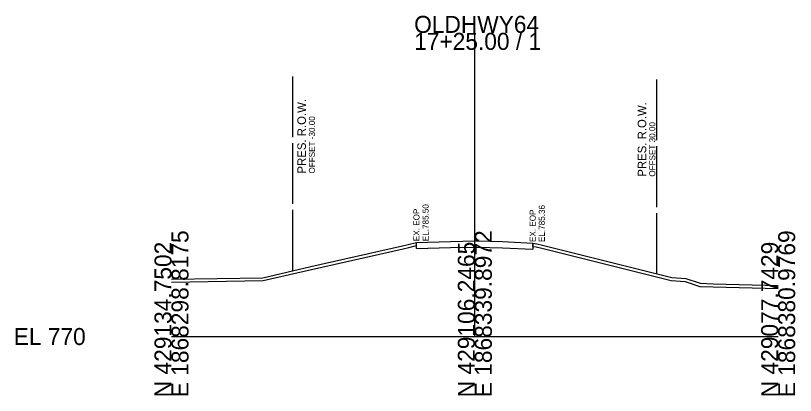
# Model space of a CAD drawing. Extents: x -452 to 3103, y -29 to 1600.
# Drawn here: x 2974.3 to 3102.8, y -16.7 to 45.8 of the extents above; entities that cross this region are included whole.
import ezdxf

# ---------------------------------------------------------------- set-up
doc = ezdxf.new("R2010")
doc.units = 0
for name, color, linetype in [('DESIGN - SHEET - Light Grid', 7, 'Continuous'), ('SURVEY - GROUND - Bottom of Topsoil Layer', 7, 'Continuous'), ('SURVEY - GROUND - Existing Pavement Layer', 7, 'Continuous'), ('SURVEY - GROUND - Existing Pavement Text', 7, 'Continuous'), ('SURVEY - GROUND - Top of Ground', 7, 'Continuous'), ('SURVEY - PROPERTY - ROW Lines', 7, 'Continuous'), ('SURVEY - PROPERTY - ROW Lines Text', 7, 'Continuous')]:
    doc.layers.add(name, color=color, linetype=linetype)

msp = doc.modelspace()

# ---------------------------------------------------------------- linework, layer by layer
at = {"layer": 'DESIGN - SHEET - Light Grid'}
for p, q in [((3050, -7), (3050, 43)), ((3000, -7), (3050, -7)), ((3050, -7), (3100, -7))]:
    msp.add_line(p, q, dxfattribs=at)
at = {"layer": 'SURVEY - GROUND - Bottom of Topsoil Layer'}
for p, q in [((3040.38, 7.99), (3040.38, 8.5)), ((3059.54, 7.85), (3059.54, 8.36))]:
    msp.add_line(p, q, dxfattribs=at)
for points in [[(3000.01, 1.93), (3015.1, 2.2), (3023.07, 4.04), (3038.2, 7.46), (3039.11, 7.67), (3040.38, 7.99)], [(3059.54, 7.85), (3060.11, 7.76), (3061.02, 7.54), (3082.37, 2.22), (3084.68, 2.06), (3087.06, 1.26), (3089.29, 1.18), (3099.99, 0.91)]]:
    msp.add_lwpolyline(points, dxfattribs=at)
at = {"layer": 'SURVEY - GROUND - Existing Pavement Layer'}
for p, q in [((3040.38, 7.5), (3040.38, 8.5)), ((3045.98, 7.64), (3050, 7.74)), ((3050, 7.74), (3050.33, 7.74)), ((3050.33, 7.74), (3054.55, 7.62)), ((3059.54, 8.36), (3059.54, 7.36)), ((3040.38, 7.5), (3045.98, 7.64)), ((3054.55, 7.62), (3059.54, 7.36))]:
    msp.add_line(p, q, dxfattribs=at)
at = {"layer": 'SURVEY - GROUND - Top of Ground'}
msp.add_lwpolyline([(3000, 2.43), (3015.04, 2.69), (3022.96, 4.53), (3038.09, 7.95), (3039, 8.16), (3040.38, 8.5), (3045.98, 8.64), (3050, 8.74), (3050.33, 8.74), (3054.55, 8.62), (3059.54, 8.36), (3060.21, 8.25), (3061.14, 8.03), (3082.45, 2.71), (3084.78, 2.56), (3087.15, 1.76), (3089.3, 1.68), (3100, 1.41)], dxfattribs=at)
at = {"layer": 'SURVEY - PROPERTY - ROW Lines'}
for p, q in [((3020, 25.84), (3020, 35.84)), ((3080, 25.32), (3080, 35.32)), ((3020, 14.84), (3020, 24.84)), ((3080, 14.32), (3080, 24.32)), ((3020, 3.84), (3020, 13.84)), ((3080, 3.32), (3080, 13.32))]:
    msp.add_line(p, q, dxfattribs=at)

# ---------------------------------------------------------------- texts
at = {"layer": 'DESIGN - SHEET - Light Grid'}
for s, p in [('OLDHWY64', (3040, 43)), ('17+25.00 / 1', (3040, 40.2)), ('EL 770', (2974, -8.4))]:
    msp.add_text(s, height=2.8, dxfattribs=at).set_placement(p)
for s, p in [('E 1868298.8175', (3002.8, -17)), ('E 1868339.8972', (3052.8, -17)), ('E 1868380.9769', (3102.8, -17)), ('N 429134.7502', (3000, -17)), ('N 429106.2465', (3050, -17)), ('N 429077.7429', (3100, -17))]:
    msp.add_text(s, height=2.8, rotation=90, dxfattribs=at).set_placement(p)
at = {"layer": 'SURVEY - GROUND - Existing Pavement Text'}
for s, p in [('EL.785.50', (3042.38, 8.7)), ('EL.785.36', (3061.54, 8.56)), ('EX. EOP', (3040.88, 8.7)), ('EX. EOP', (3060.04, 8.56))]:
    msp.add_text(s, height=1, rotation=90, dxfattribs=at).set_placement(p)
at = {"layer": 'SURVEY - PROPERTY - ROW Lines Text'}
for s, height, p in [('PRES. R.O.W.', 1.4, (3022.15, 19.84)), ('PRES. R.O.W.', 1.4, (3078.25, 19.32)), ('OFFSET -30.00', 1, (3023.65, 19.84)), ('OFFSET 30.00', 1, (3079.75, 19.32))]:
    msp.add_text(s, height=height, rotation=90, dxfattribs=at).set_placement(p)

doc.saveas('drawing.dxf')
